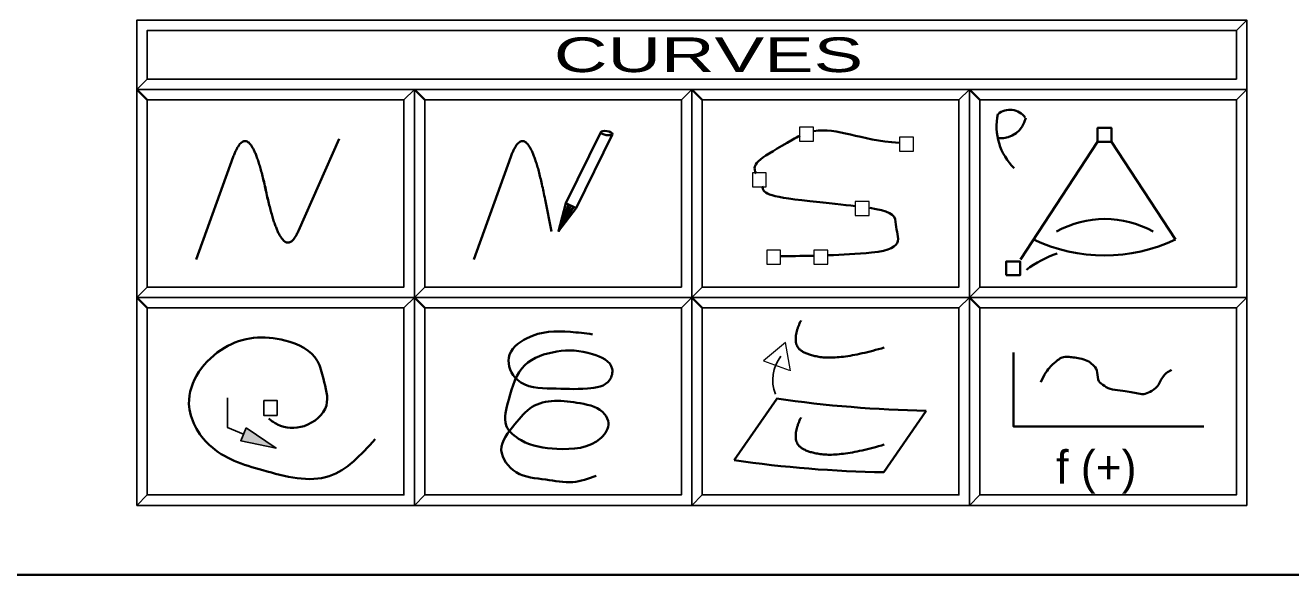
# Model space of a CAD drawing. Extents: x 95906.9 to 95918.9, y 90964.8 to 90972.9.
# Drawn here: x 95914.369 to 95916.193, y 90964.762 to 90965.554 of the extents above; entities that cross this region are included whole.
import ezdxf
from ezdxf.enums import TextEntityAlignment as Align

# ---------------------------------------------------------------- set-up
doc = ezdxf.new("R2010")
doc.units = 0
doc.header["$LTSCALE"] = 0.019
for name, color, linetype, lineweight in [('1', 7, 'Continuous', 25), ('11', 7, 'Continuous', 25), ('12', 7, 'Continuous', 25), ('17', 7, 'Continuous', 25), ('2', 7, 'Continuous', 13), ('3', 7, 'Continuous', 25), ('4', 7, 'Continuous', 35), ('6', 7, 'Continuous', 35), ('7', 7, 'Continuous', 35)]:
    doc.layers.add(name, color=color, linetype=linetype, lineweight=lineweight)

msp = doc.modelspace()

# ---------------------------------------------------------------- hatches: boundary and pattern name
at = {"layer": '6'}
msp.add_hatch(color=256, dxfattribs=at).paths.add_polyline_path([(95914.6873, 90964.9736), (95914.7305, 90964.9443), (95914.6794, 90964.9549)])

# ---------------------------------------------------------------- linework, layer by layer
at = {"layer": '1'}
for points in [[(95914.5298, 90965.4617), (95916.1298, 90965.4617), (95916.1298, 90965.5617), (95914.5298, 90965.5617)], [(95914.5298, 90965.1617), (95914.9298, 90965.1617), (95914.9298, 90965.4617), (95914.5298, 90965.4617)], [(95914.9298, 90965.1617), (95915.3298, 90965.1617), (95915.3298, 90965.4617), (95914.9298, 90965.4617)], [(95915.3298, 90965.1617), (95915.7298, 90965.1617), (95915.7298, 90965.4617), (95915.3298, 90965.4617)], [(95915.7298, 90965.1617), (95916.1298, 90965.1617), (95916.1298, 90965.4617), (95915.7298, 90965.4617)], [(95914.5298, 90964.8617), (95914.9298, 90964.8617), (95914.9298, 90965.1617), (95914.5298, 90965.1617)], [(95914.9298, 90964.8617), (95915.3298, 90964.8617), (95915.3298, 90965.1617), (95914.9298, 90965.1617)], [(95915.3298, 90964.8617), (95915.7298, 90964.8617), (95915.7298, 90965.1617), (95915.3298, 90965.1617)], [(95915.7298, 90964.8617), (95916.1298, 90964.8617), (95916.1298, 90965.1617), (95915.7298, 90965.1617)]]:
    msp.add_lwpolyline(points, close=True, dxfattribs=at)
at = {"layer": '11'}
for points in [[(95914.5448, 90965.1767), (95914.9148, 90965.1767), (95914.9148, 90965.4467), (95914.5448, 90965.4467)], [(95914.9448, 90965.1767), (95915.3148, 90965.1767), (95915.3148, 90965.4467), (95914.9448, 90965.4467)], [(95915.3448, 90965.1767), (95915.7148, 90965.1767), (95915.7148, 90965.4467), (95915.3448, 90965.4467)], [(95915.7448, 90965.1767), (95916.1148, 90965.1767), (95916.1148, 90965.4467), (95915.7448, 90965.4467)], [(95914.5448, 90964.8767), (95914.9148, 90964.8767), (95914.9148, 90965.1467), (95914.5448, 90965.1467)], [(95914.9448, 90964.8767), (95915.3148, 90964.8767), (95915.3148, 90965.1467), (95914.9448, 90965.1467)], [(95915.3448, 90964.8767), (95915.7148, 90964.8767), (95915.7148, 90965.1467), (95915.3448, 90965.1467)], [(95915.7448, 90964.8767), (95916.1148, 90964.8767), (95916.1148, 90965.1467), (95915.7448, 90965.1467)]]:
    msp.add_lwpolyline(points, close=True, dxfattribs=at)
at = {"layer": '12'}
msp.add_lwpolyline([(95914.5448, 90965.1767), (95914.9148, 90965.1767), (95914.9148, 90965.4467), (95914.5448, 90965.4467)], close=True, dxfattribs=at)
at = {"layer": '17'}
msp.add_lwpolyline([(95914.5448, 90965.4767), (95916.1148, 90965.4767), (95916.1148, 90965.5467), (95914.5448, 90965.5467)], close=True, dxfattribs=at)
at = {"layer": '2'}
for points in [[(95914.5298, 90965.5617), (95914.5298, 90965.4617), (95914.5448, 90965.4767), (95914.5448, 90965.5467), (95916.1148, 90965.5467), (95916.1298, 90965.5617)], [(95914.5298, 90965.4617), (95914.5298, 90965.1617), (95914.5448, 90965.1767), (95914.5448, 90965.4467), (95914.9148, 90965.4467), (95914.9298, 90965.4617)], [(95914.9298, 90965.4617), (95914.9298, 90965.1617), (95914.9448, 90965.1767), (95914.9448, 90965.4467), (95915.3148, 90965.4467), (95915.3298, 90965.4617)], [(95915.3298, 90965.4617), (95915.3298, 90965.1617), (95915.3448, 90965.1767), (95915.3448, 90965.4467), (95915.7148, 90965.4467), (95915.7298, 90965.4617)], [(95915.7298, 90965.4617), (95915.7298, 90965.1617), (95915.7448, 90965.1767), (95915.7448, 90965.4467), (95916.1148, 90965.4467), (95916.1298, 90965.4617)], [(95914.5298, 90965.1617), (95914.5298, 90964.8617), (95914.5448, 90964.8767), (95914.5448, 90965.1467), (95914.9148, 90965.1467), (95914.9298, 90965.1617)], [(95914.9298, 90965.1617), (95914.9298, 90964.8617), (95914.9448, 90964.8767), (95914.9448, 90965.1467), (95915.3148, 90965.1467), (95915.3298, 90965.1617)], [(95915.3298, 90965.1617), (95915.3298, 90964.8617), (95915.3448, 90964.8767), (95915.3448, 90965.1467), (95915.7148, 90965.1467), (95915.7298, 90965.1617)], [(95915.7298, 90965.1617), (95915.7298, 90964.8617), (95915.7448, 90964.8767), (95915.7448, 90965.1467), (95916.1148, 90965.1467), (95916.1298, 90965.1617)]]:
    msp.add_lwpolyline(points, close=True, dxfattribs=at)
at = {"layer": '3'}
for points in [[(95914.5298, 90965.4617), (95916.1298, 90965.4617), (95916.1298, 90965.5617), (95916.1148, 90965.5467), (95916.1148, 90965.4767), (95914.5448, 90965.4767)], [(95914.5298, 90965.1617), (95914.9298, 90965.1617), (95914.9298, 90965.4617), (95914.9148, 90965.4467), (95914.9148, 90965.1767), (95914.5448, 90965.1767)], [(95914.9298, 90965.1617), (95915.3298, 90965.1617), (95915.3298, 90965.4617), (95915.3148, 90965.4467), (95915.3148, 90965.1767), (95914.9448, 90965.1767)], [(95915.3298, 90965.1617), (95915.7298, 90965.1617), (95915.7298, 90965.4617), (95915.7148, 90965.4467), (95915.7148, 90965.1767), (95915.3448, 90965.1767)], [(95915.7298, 90965.1617), (95916.1298, 90965.1617), (95916.1298, 90965.4617), (95916.1148, 90965.4467), (95916.1148, 90965.1767), (95915.7448, 90965.1767)], [(95914.5298, 90964.8617), (95914.9298, 90964.8617), (95914.9298, 90965.1617), (95914.9148, 90965.1467), (95914.9148, 90964.8767), (95914.5448, 90964.8767)], [(95914.9298, 90964.8617), (95915.3298, 90964.8617), (95915.3298, 90965.1617), (95915.3148, 90965.1467), (95915.3148, 90964.8767), (95914.9448, 90964.8767)], [(95915.3298, 90964.8617), (95915.7298, 90964.8617), (95915.7298, 90965.1617), (95915.7148, 90965.1467), (95915.7148, 90964.8767), (95915.3448, 90964.8767)], [(95915.7298, 90964.8617), (95916.1298, 90964.8617), (95916.1298, 90965.1617), (95916.1148, 90965.1467), (95916.1148, 90964.8767), (95915.7448, 90964.8767)]]:
    msp.add_lwpolyline(points, close=True, dxfattribs=at)
at = {"layer": '4'}
for p, q in [((95914.5448, 90965.4467), (95914.5298, 90965.4617)), ((95914.9448, 90965.4467), (95914.9298, 90965.4617)), ((95915.3448, 90965.4467), (95915.3298, 90965.4617)), ((95915.7448, 90965.4467), (95915.7298, 90965.4617)), ((95914.5448, 90965.1467), (95914.5298, 90965.1617)), ((95914.9448, 90965.1467), (95914.9298, 90965.1617)), ((95915.3448, 90965.1467), (95915.3298, 90965.1617)), ((95915.7448, 90965.1467), (95915.7298, 90965.1617))]:
    msp.add_line(p, q, dxfattribs=at)
at = {"layer": '6'}
for p, q in [((95915.1984, 90965.4), (95915.1481, 90965.2978)), ((95915.2153, 90965.3973), (95915.1628, 90965.2906)), ((95914.7626, 90965.2577), (95914.8214, 90965.3905)), ((95915.9146, 90965.3861), (95915.8035, 90965.2166)), ((95915.9346, 90965.3861), (95916.0271, 90965.245)), ((95914.6154, 90965.2162), (95914.6687, 90965.3644)), ((95915.0154, 90965.2162), (95915.0687, 90965.3644)), ((95915.1182, 90965.3029), (95915.1276, 90965.2569)), ((95915.1374, 90965.2574), (95915.152, 90965.2959)), ((95915.1555, 90965.2942), (95915.1374, 90965.2574)), ((95915.4522, 90965.0154), (95915.3909, 90964.9269)), ((95915.6677, 90964.9983), (95915.6067, 90964.9094))]:
    msp.add_line(p, q, dxfattribs=at)
at = {"layer": '6', "lineweight": 13}
msp.add_line((95915.433, 90965.0701), (95915.4702, 90965.0566), dxfattribs=at)
for points in [[(95915.485, 90965.3871), (95915.505, 90965.3871), (95915.505, 90965.4071), (95915.485, 90965.4071)], [(95915.6291, 90965.3727), (95915.6491, 90965.3727), (95915.6491, 90965.3927), (95915.6291, 90965.3927)], [(95915.417, 90965.3212), (95915.437, 90965.3212), (95915.437, 90965.3412), (95915.417, 90965.3412)], [(95915.5653, 90965.28), (95915.5853, 90965.28), (95915.5853, 90965.3), (95915.5653, 90965.3)], [(95915.4377, 90965.2098), (95915.4577, 90965.2098), (95915.4577, 90965.2298), (95915.4377, 90965.2298)], [(95915.5056, 90965.2098), (95915.5256, 90965.2098), (95915.5256, 90965.2298), (95915.5056, 90965.2298)]]:
    msp.add_lwpolyline(points, close=True, dxfattribs=at)
at = {"layer": '6'}
for points in [[(95915.9146, 90965.3861), (95915.9346, 90965.3861), (95915.9346, 90965.4061), (95915.9146, 90965.4061)], [(95915.9146, 90965.3861), (95915.9346, 90965.3861), (95915.9346, 90965.4061), (95915.9146, 90965.4061)], [(95915.783, 90965.1936), (95915.803, 90965.1936), (95915.803, 90965.2136), (95915.783, 90965.2136)]]:
    msp.add_lwpolyline(points, close=True, dxfattribs=at)
for points in [[(95915.1481, 90965.2978), (95915.1628, 90965.2906), (95915.1374, 90965.2574)], [(95915.1481, 90965.2978), (95915.1374, 90965.2574), (95915.159, 90965.2923)], [(95916.0679, 90964.9754), (95915.7936, 90964.9754), (95915.7936, 90965.0824)]]:
    msp.add_lwpolyline(points, dxfattribs=at)
at = {"layer": '6', "lineweight": 13}
msp.add_lwpolyline([(95915.4722, 90965.0558), (95915.4649, 90965.0968), (95915.433, 90965.0701)], dxfattribs=at)
at = {"layer": '6', "lineweight": 25}
msp.add_lwpolyline([(95914.6602, 90965.0167), (95914.6602, 90964.9741), (95914.6834, 90964.9643)], dxfattribs=at)
for points in [[(95914.7126, 90965.0131), (95914.7318, 90965.0131), (95914.7318, 90964.9915), (95914.7126, 90964.9915)], [(95914.6873, 90964.9736), (95914.7305, 90964.9443), (95914.6794, 90964.9549)]]:
    msp.add_lwpolyline(points, close=True, dxfattribs=at)
at = {"layer": '6'}
for centre, radius, start, end in [((95915.7885, 90965.4053), 0.027, 36.5372, 129.7193), ((95915.8539, 90965.4087), 0.0849, 168.1659, 225.5957), ((95915.7748, 90965.4283), 0.037, 266.271, 347.9424), ((95915.9251, 90965.1334), 0.1415, 60.5317, 119.4682), ((95915.9246, 90965.4646), 0.2423, 244.9787, 295.0213), ((95915.9107, 90965.0697), 0.1646, 109.2772, 126.814), ((95915.6994, 90966.7405), 1.7425, 261.8343, 268.9564), ((95915.6384, 90966.6516), 1.7425, 261.8343, 268.9564)]:
    msp.add_arc(centre, radius, start, end, dxfattribs=at)
at = {"layer": '6', "lineweight": 25}
msp.add_arc((95915.5018, 90965.0426), 0.0555, 141.7923, 201.5664, dxfattribs=at)
at = {"layer": '6'}
msp.add_ellipse((95915.2069, 90965.3987), major_axis=(0.00845, -0.00135), ratio=0.335575, dxfattribs=at)
for points, degree in [([(95915.6285, 90965.3847), (95915.5707, 90965.3884), (95915.5399, 90965.4073), (95915.5057, 90965.4015)], 3), ([(95915.4751, 90965.3895), (95915.4303, 90965.3626), (95915.4139, 90965.3559), (95915.4223, 90965.3402)], 3), ([(95915.4857, 90965.3951), (95915.4823, 90965.3936), (95915.4787, 90965.3917), (95915.4751, 90965.3895)], 3), ([(95915.4312, 90965.322), (95915.4331, 90965.3123), (95915.4347, 90965.3077), (95915.4998, 90965.3005)], 3), ([(95915.4998, 90965.3005), (95915.5266, 90965.2975), (95915.5484, 90965.2954), (95915.5659, 90965.2934)], 3), ([(95915.5865, 90965.2907), (95915.6123, 90965.2868), (95915.6234, 90965.2819), (95915.6234, 90965.2707)], 3), ([(95915.6234, 90965.2707), (95915.6234, 90965.251), (95915.6433, 90965.2314), (95915.5889, 90965.2263)], 3), ([(95915.5058, 90965.2218), (95915.4864, 90965.2213), (95915.4699, 90965.2213), (95915.4585, 90965.2213)], 3), ([(95915.5889, 90965.2263), (95915.5674, 90965.2243), (95915.546, 90965.2231), (95915.5264, 90965.2224)], 3), ([(95915.4872, 90965.1286), (95915.4764, 90965.107), (95915.4849, 90965.0803), (95915.5446, 90965.0711), (95915.6072, 90965.0894)], 2), ([(95915.8328, 90965.0395), (95915.8378, 90965.0512), (95915.8476, 90965.0638), (95915.8577, 90965.0716), (95915.8631, 90965.0757), (95915.8722, 90965.0762), (95915.8791, 90965.0752), (95915.8888, 90965.0738), (95915.9006, 90965.0709), (95915.9076, 90965.0645), (95915.9149, 90965.0578), (95915.914, 90965.0417), (95915.9218, 90965.036), (95915.9318, 90965.0287), (95915.9477, 90965.0274), (95915.961, 90965.0253), (95915.9703, 90965.0238), (95915.9817, 90965.0212), (95915.9895, 90965.0253), (95916.0019, 90965.0319), (95916.0093, 90965.0505), (95916.0177, 90965.0552), (95916.021, 90965.0571), (95916.0212, 90965.0572)], 3), ([(95915.4872, 90964.9886), (95915.4764, 90964.967), (95915.4849, 90964.9403), (95915.5446, 90964.9311), (95915.6072, 90964.9494)], 2)]:
    msp.add_open_spline(points, degree=degree, dxfattribs=at)
for points in [[(95914.7182, 90965.3029), (95914.7159, 90965.3143), (95914.7136, 90965.3249), (95914.7113, 90965.3345), (95914.7091, 90965.3435), (95914.7068, 90965.3516), (95914.7045, 90965.3588), (95914.7022, 90965.3653), (95914.7, 90965.3709), (95914.6977, 90965.3757), (95914.6954, 90965.3796), (95914.6932, 90965.3827), (95914.6909, 90965.385), (95914.6886, 90965.3865), (95914.6863, 90965.3872), (95914.6841, 90965.387), (95914.6818, 90965.3861), (95914.6795, 90965.3843), (95914.6772, 90965.3817), (95914.675, 90965.3782), (95914.6727, 90965.3739), (95914.6704, 90965.3689), (95914.6682, 90965.3629)], [(95915.1182, 90965.3029), (95915.1159, 90965.3143), (95915.1136, 90965.3249), (95915.1113, 90965.3345), (95915.1091, 90965.3435), (95915.1068, 90965.3516), (95915.1045, 90965.3588), (95915.1022, 90965.3653), (95915.1, 90965.3709), (95915.0977, 90965.3757), (95915.0954, 90965.3796), (95915.0932, 90965.3827), (95915.0909, 90965.385), (95915.0886, 90965.3865), (95915.0863, 90965.3872), (95915.0841, 90965.387), (95915.0818, 90965.3861), (95915.0795, 90965.3843), (95915.0772, 90965.3817), (95915.075, 90965.3782), (95915.0727, 90965.3739), (95915.0704, 90965.3689), (95915.0682, 90965.3629)], [(95914.7627, 90965.2578), (95914.7604, 90965.253), (95914.7581, 90965.2491), (95914.7559, 90965.2459), (95914.7536, 90965.2434), (95914.7513, 90965.2417), (95914.7491, 90965.2409), (95914.7468, 90965.2408), (95914.7445, 90965.2414), (95914.7422, 90965.2428), (95914.74, 90965.245), (95914.7377, 90965.248), (95914.7354, 90965.2517), (95914.7331, 90965.2562), (95914.7309, 90965.2615), (95914.7286, 90965.2675), (95914.7263, 90965.2743), (95914.7241, 90965.2819), (95914.7218, 90965.2903), (95914.7195, 90965.2994), (95914.7172, 90965.3093), (95914.715, 90965.32), (95914.7127, 90965.3314)], [(95914.7198, 90964.9869), (95914.7326, 90964.9783), (95914.7709, 90964.9762), (95914.8029, 90965.006), (95914.7986, 90965.0443), (95914.7901, 90965.0699), (95914.7432, 90965.0997), (95914.6559, 90965.0891), (95914.6048, 90965.0081), (95914.6346, 90964.9485), (95914.7113, 90964.9123), (95914.8071, 90964.9038), (95914.8731, 90964.957)], [(95915.1865, 90965.1084), (95915.1546, 90965.112), (95915.0924, 90965.1031), (95915.0658, 90965.0747), (95915.0782, 90965.0427), (95915.1279, 90965.0303), (95915.1794, 90965.0303), (95915.2114, 90965.0427), (95915.2149, 90965.0587), (95915.1865, 90965.08), (95915.135, 90965.0836), (95915.0889, 90965.064), (95915.0658, 90965.0143), (95915.0622, 90964.977), (95915.0835, 90964.9557), (95915.135, 90964.9433), (95915.199, 90964.9593), (95915.2096, 90964.9806), (95915.2043, 90964.993), (95915.1688, 90965.009), (95915.0995, 90965.0037), (95915.0747, 90964.9788), (95915.0551, 90964.9415), (95915.0764, 90964.9096), (95915.1191, 90964.8989), (95915.1581, 90964.8954), (95915.1919, 90964.9042)]]:
    msp.add_spline(points, degree=3, dxfattribs=at)
at = {"layer": '7'}
msp.add_lwpolyline([(95906.8548, 90972.8617), (95918.8548, 90972.8617), (95918.8548, 90964.7617), (95906.8548, 90964.7617)], close=True, dxfattribs=at)

# ---------------------------------------------------------------- texts
at = {"layer": '6'}
msp.add_text('f (+)', height=0.048, dxfattribs=at).set_placement((95915.9128, 90964.8929), align=Align.CENTER)
at = {"layer": '7', "width": 1.6}
msp.add_text('      CURVES     ', height=0.05, dxfattribs=at).set_placement((95915.3389, 90965.4867), align=Align.CENTER)

doc.saveas('drawing.dxf')
